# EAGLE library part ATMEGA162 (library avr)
MIKROCONTROLLER ATmega162 16kB Flash 2kB RAM 2 USARTS ATmega162 = 2,7-5,5V or ATmega162V = 1,8-5,5V
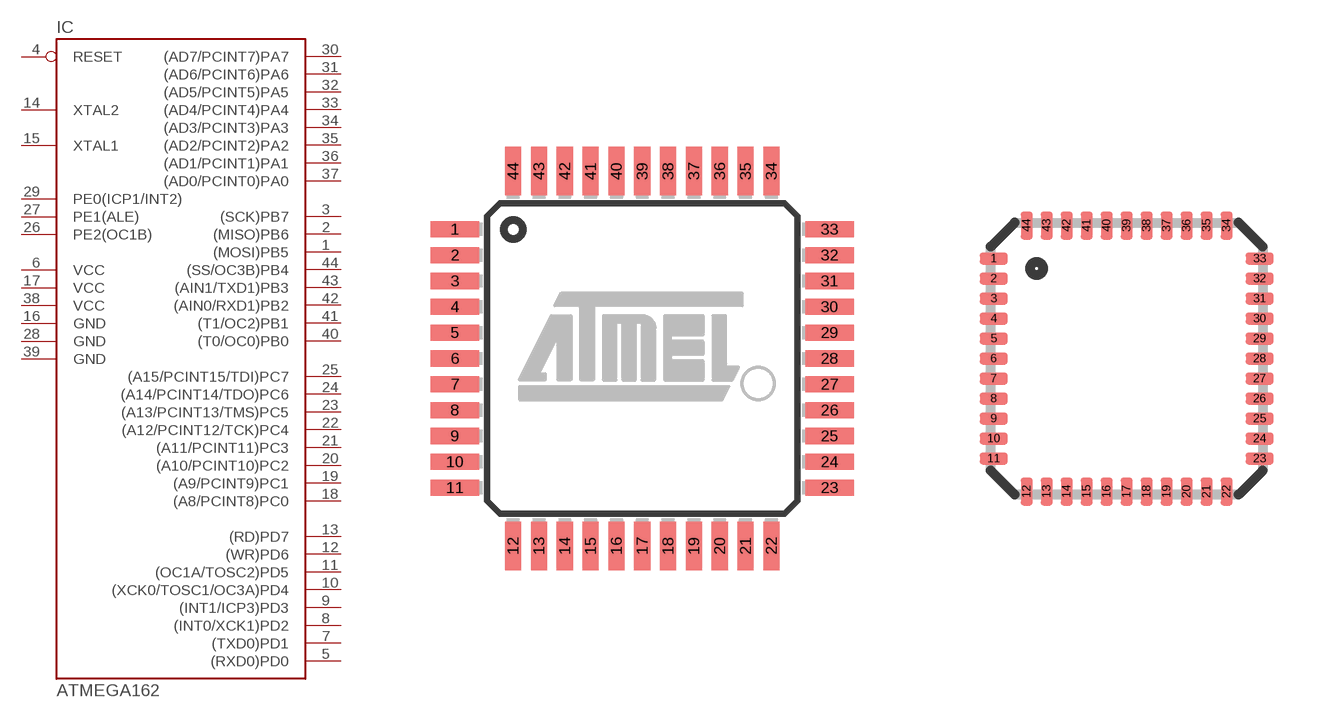
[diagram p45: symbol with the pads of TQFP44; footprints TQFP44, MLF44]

Designator prefix IC

## ATMEGA162-16A, ATMEGA162V-8A  [TQFP44]
1  (MOSI)PB5
2  (MISO)PB6
3  (SCK)PB7
4  RESET  in
5  (RXD0)PD0
6  VCC  pwr
7  (TXD0)PD1
8  (INT0/XCK1)PD2
9  (INT1/ICP3)PD3
10  (XCK0/TOSC1/OC3A)PD4
11  (OC1A/TOSC2)PD5
12  (WR)PD6
13  (RD)PD7
14  XTAL2
15  XTAL1
16  GND  pwr
17  VCC  pwr
18  (A8/PCINT8)PC0
19  (A9/PCINT9)PC1
20  (A10/PCINT10)PC2
21  (A11/PCINT11)PC3
22  (A12/PCINT12/TCK)PC4
23  (A13/PCINT13/TMS)PC5
24  (A14/PCINT14/TDO)PC6
25  (A15/PCINT15/TDI)PC7
26  PE2(OC1B)
27  PE1(ALE)
28  GND  pwr
29  PE0(ICP1/INT2)
30  (AD7/PCINT7)PA7
31  (AD6/PCINT6)PA6
32  (AD5/PCINT5)PA5
33  (AD4/PCINT4)PA4
34  (AD3/PCINT3)PA3
35  (AD2/PCINT2)PA2
36  (AD1/PCINT1)PA1
37  (AD0/PCINT0)PA0
38  VCC  pwr
39  GND  pwr
40  (T0/OC0)PB0
41  (T1/OC2)PB1
42  (AIN0/RXD1)PB2
43  (AIN1/TXD1)PB3
44  (SS/OC3B)PB4

## ATMEGA162-16M, ATMEGA162V-8M  [MLF44]
Pads as for TQFP44

## Footprint TQFP44 (pad centres in mm)
Thin Plasic Quad Flat Package
smd 1.5 x 0.5: 1 -5.8,4; 2 -5.8,3.2; 3 -5.8,2.4; 4 -5.8,1.6; 5 -5.8,0.8; 6 -5.8,0; 7 -5.8,-0.8; 8 -5.8,-1.6; 9 -5.8,-2.4; 10 -5.8,-3.2; 11 -5.8,-4; 23 5.8,-4; 24 5.8,-3.2; 25 5.8,-2.4; 26 5.8,-1.6; 27 5.8,-0.8; 28 5.8,0; 29 5.8,0.8; 30 5.8,1.6; 31 5.8,2.4; 32 5.8,3.2; 33 5.8,4
smd 0.5 x 1.5: 12 -4,-5.8; 13 -3.2,-5.8; 14 -2.4,-5.8; 15 -1.6,-5.8; 16 -0.8,-5.8; 17 0,-5.8; 18 0.8,-5.8; 19 1.6,-5.8; 20 2.4,-5.8; 21 3.2,-5.8; 22 4,-5.8; 34 4,5.8; 35 3.2,5.8; 36 2.4,5.8; 37 1.6,5.8; 38 0.8,5.8; 39 0,5.8; 40 -0.8,5.8; 41 -1.6,5.8; 42 -2.4,5.8; 43 -3.2,5.8; 44 -4,5.8

## Footprint MLF44 (pad centres in mm)
44M1 Micro Lead Frame package (MLF)
smd 0.7 x 0.3: 1 -3.325,2.5; 2 -3.325,2; 3 -3.325,1.5; 4 -3.325,1; 5 -3.325,0.5; 6 -3.325,0; 7 -3.325,-0.5; 8 -3.325,-1; 9 -3.325,-1.5; 10 -3.325,-2; 11 -3.325,-2.5; 23 3.325,-2.5; 24 3.325,-2; 25 3.325,-1.5; 26 3.325,-1; 27 3.325,-0.5; 28 3.325,0; 29 3.325,0.5; 30 3.325,1; 31 3.325,1.5; 32 3.325,2; 33 3.325,2.5
smd 0.3 x 0.7: 12 -2.5,-3.325; 13 -2,-3.325; 14 -1.5,-3.325; 15 -1,-3.325; 16 -0.5,-3.325; 17 0,-3.325; 18 0.5,-3.325; 19 1,-3.325; 20 1.5,-3.325; 21 2,-3.325; 22 2.5,-3.325; 34 2.5,3.325; 35 2,3.325; 36 1.5,3.325; 37 1,3.325; 38 0.5,3.325; 39 0,3.325; 40 -0.5,3.325; 41 -1,3.325; 42 -1.5,3.325; 43 -2,3.325; 44 -2.5,3.325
